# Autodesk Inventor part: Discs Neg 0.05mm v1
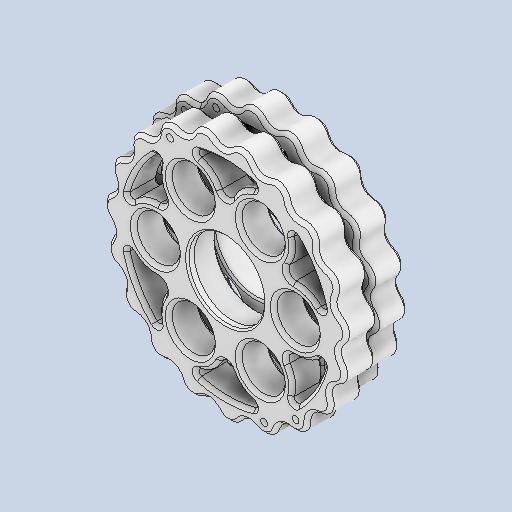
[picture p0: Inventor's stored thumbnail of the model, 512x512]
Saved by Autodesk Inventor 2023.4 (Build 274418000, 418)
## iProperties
Created: 2025-06
Part Number: Discs Neg 0.05mm v1
Material: Steel
Document SubType Name: Modeling
Designer: mel
Density: 7.85 g/cm^3
Appearance: Par défaut
Author: mel
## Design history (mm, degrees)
feature "Discs Neg 0.05mm"
feature "Discs Neg 0.05mm Bottom"
node "Solide1"
node "Solide2"
